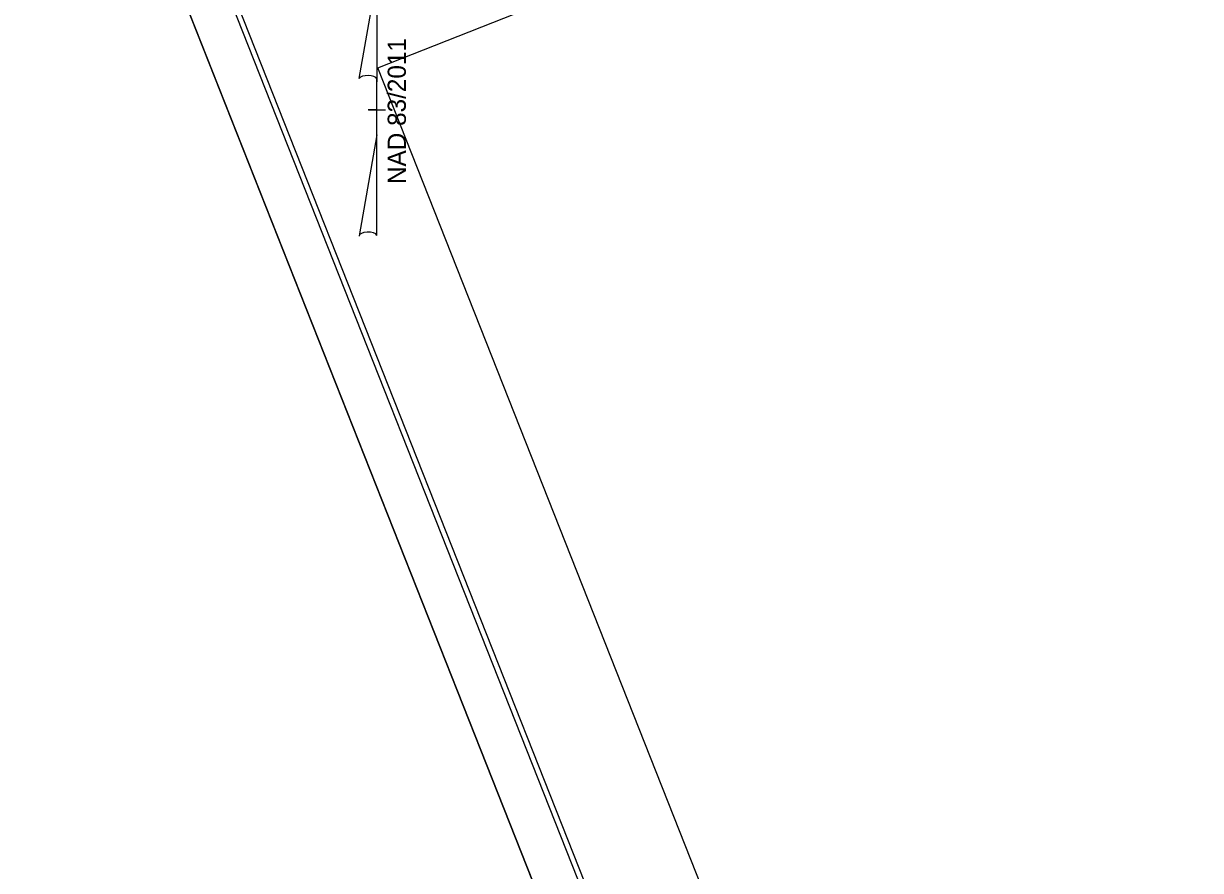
# Model space of a CAD drawing. Extents: x 1250120 to 1251758, y 748130 to 750098.
# Drawn here: x 1250120 to 1250670, y 749099 to 749494 of the extents above; entities that cross this region are included whole.
import ezdxf

# ---------------------------------------------------------------- set-up
doc = ezdxf.new("R2010")
doc.units = 0
for name, color, linetype in [('Prop North Arrow for Plan Sheets CELL', 7, 'Continuous'), ('Prop North Arrow NAD83 for Plan Sheets CELL', 7, 'Continuous'), ('Sheet Cutting Line CELL', 7, 'Continuous'), ('Sheet Layout Plan Border', 7, 'Continuous'), ('Sheet North Arrow Point CELL', 7, 'Continuous'), ('Sheet Plan And Profile CELL', 7, 'Continuous'), ('Sheet Plot Border Inside CELL', 7, 'Continuous'), ('Sheet Plot Border Outside CELL', 7, 'Continuous')]:
    doc.layers.add(name, color=color, linetype=linetype)

msp = doc.modelspace()

# ---------------------------------------------------------------- linework, layer by layer
at = {"layer": 'Prop North Arrow for Plan Sheets CELL'}
for p, q in [((1250277.24, 749468.71), (1250285.44, 749515.06)), ((1250285.49, 749515.06), (1250285.49, 749467.26)), ((1250285.49, 749442.46), (1250285.49, 749468.66)), ((1250285.49, 749467.26), (1250285.49, 749468.61)), ((1250281.49, 749454.06), (1250281.44, 749454.06)), ((1250285.04, 749454.06), (1250281.49, 749454.06)), ((1250281.54, 749454.06), (1250289.54, 749454.06)), ((1250285.49, 749442.46), (1250277.14, 749395.21)), ((1250285.54, 749395.41), (1250285.49, 749442.46))]:
    msp.add_line(p, q, dxfattribs=at)
for centre, start_param, end_param in [((1250281.38, 749468.22), 0.216388, 2.908219), ((1250281.38, 749395.05), 0.201328, 3.141593)]:
    msp.add_ellipse(centre, major_axis=(4.23, -0.03), ratio=0.461098, start_param=start_param, end_param=end_param, dxfattribs=at)
at = {"layer": 'Sheet Cutting Line CELL'}
msp.add_line((1250120.32, 749695.34), (1250739.35, 748129.79), dxfattribs=at)
at = {"layer": 'Sheet Layout Plan Border'}
msp.add_lwpolyline([(1251145.64, 748523.25), (1250727.17, 748357.78), (1250285.93, 749473.66), (1250436.11, 749533.04), (1250362.55, 749719.08), (1250630.85, 749825.16)], close=True, dxfattribs=at)
at = {"layer": 'Sheet North Arrow Point CELL'}
msp.add_line((1250285.54, 749454.06), (1250285.54, 749454.06), dxfattribs=at)
at = {"layer": 'Sheet Plan And Profile CELL'}
msp.add_lwpolyline([(1250147.49, 749687.81), (1250699.05, 748292.9), (1251675.49, 748678.99), (1251123.93, 750073.9)], close=True, dxfattribs=at)
at = {"layer": 'Sheet Plot Border Inside CELL'}
msp.add_lwpolyline([(1251734.26, 748537.16), (1251121.66, 750086.44), (1250140.57, 749698.51), (1250753.17, 748149.23)], close=True, dxfattribs=at)
at = {"layer": 'Sheet Plot Border Outside CELL'}
msp.add_lwpolyline([(1251757.64, 748532.43), (1251138.6, 750097.98), (1250120.32, 749695.34), (1250739.35, 748129.79)], close=True, dxfattribs=at)

# ---------------------------------------------------------------- texts
at = {"layer": 'Prop North Arrow NAD83 for Plan Sheets CELL'}
msp.add_text('NAD 83/2011', height=8.5, rotation=90, dxfattribs=at).set_placement((1250299.04, 749419.42))

doc.saveas('drawing.dxf')
